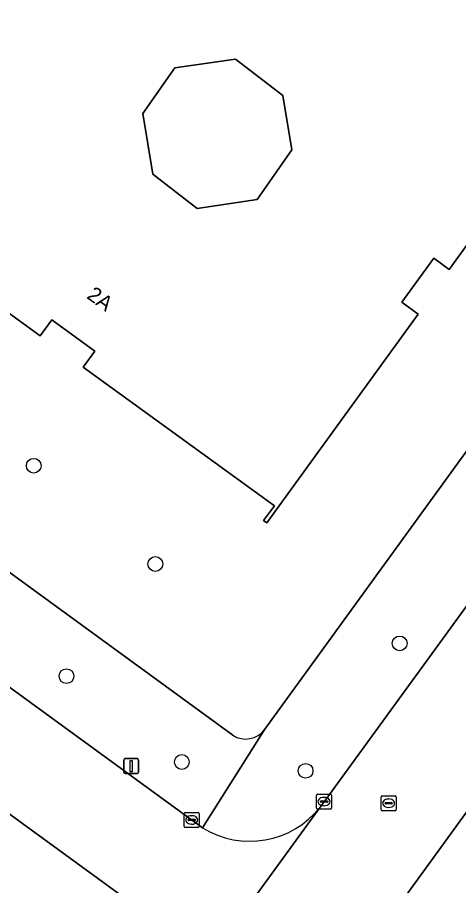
# Model space of a CAD drawing. Extents: x 159674 to 160531, y 382172 to 382904.
# Drawn here: x 160111.2 to 160140.5, y 382380.6 to 382438.2 of the extents above; entities that cross this region are included whole.
import ezdxf

# ---------------------------------------------------------------- set-up
doc = ezdxf.new("R2010")
doc.units = 0
for name, color, linetype in [('IMGEO_Boom', 7, 'Continuous'), ('IMGEO_Erf', 7, 'Continuous'), ('IMGEO_Kolk', 7, 'Continuous'), ('IMGEO_Lichtmast', 7, 'Continuous'), ('IMGEO_Pand', 7, 'Continuous'), ('IMGEO_Pand_nummerreeks', 7, 'Continuous'), ('IMGEO_Rijbaan_lokaal_gesloten', 7, 'Continuous'), ('IMGEO_Rijbaan_lokaal_open', 7, 'Continuous'), ('IMGEO_Rioolput', 7, 'Continuous'), ('IMGEO_Voetpad_open', 7, 'Continuous')]:
    doc.layers.add(name, color=color, linetype=linetype)

msp = doc.modelspace()

# ---------------------------------------------------------------- linework, layer by layer
at = {"layer": 'IMGEO_Boom'}
for centre in [(160112.252, 382408.448), (160120.326, 382401.93), (160136.553, 382396.66), (160114.425, 382394.485), (160122.087, 382388.792), (160130.305, 382388.206)]:
    msp.add_circle(centre, 0.489, dxfattribs=at)
at = {"layer": 'IMGEO_Erf'}
for points in [[(160095.853, 382488.776), (160093.109, 382485.042), (160086.78, 382476.254), (160084.42, 382472.917), (160083.291, 382471.347), (160082.163, 382469.777), (160081.035, 382468.207), (160079.906, 382466.638), (160078.778, 382465.068), (160077.649, 382463.498), (160076.521, 382461.928), (160075.392, 382460.359), (160074.264, 382458.789), (160073.136, 382457.219), (160072.007, 382455.649), (160068.6, 382451.01), (160062.271, 382442.237), (160059.604, 382438.555), (160125.462, 382390.566)], [(160127.601, 382390.967), (160163.121, 382439.912), (160095.853, 382488.776)], [(160136.317, 382443.627), (160150.083, 382433.637), (160149.925, 382433.419), (160148.987, 382434.099), (160139.829, 382421.48), (160138.814, 382422.216), (160136.697, 382419.3), (160137.776, 382418.517), (160127.72, 382404.66), (160127.519, 382404.805), (160128.233, 382405.79), (160115.542, 382415), (160116.31, 382416.057), (160113.45, 382418.133), (160112.674, 382417.064), (160100.019, 382426.248), (160099.35, 382425.327), (160099.082, 382425.521), (160110.426, 382441.152)]]:
    msp.add_lwpolyline(points, dxfattribs=at)
msp.add_lwpolyline([(160121.623, 382434.844), (160119.486, 382431.823), (160120.153, 382427.795), (160123.094, 382425.526), (160127.09, 382426.109), (160129.389, 382429.403), (160128.791, 382433.014), (160125.655, 382435.433)], close=True, dxfattribs=at)
msp.add_arc((160126.319, 382391.898), 1.584, 237.23232, 324.00376, dxfattribs=at)
at = {"layer": 'IMGEO_Kolk'}
for p, q in [((160131.028, 382385.738), (160131.028, 382386.59)), ((160131.103, 382386.664), (160131.955, 382386.664)), ((160131.516, 382386.444), (160131.541, 382386.444)), ((160132.029, 382386.59), (160132.029, 382385.738)), ((160131.287, 382386.158), (160131.287, 382386.17)), ((160131.725, 382386.121), (160131.327, 382386.121)), ((160131.33, 382386.207), (160131.728, 382386.207)), ((160131.539, 382385.884), (160131.514, 382385.884)), ((160131.771, 382386.17), (160131.771, 382386.158)), ((160122.242, 382384.521), (160122.242, 382385.373)), ((160122.317, 382385.447), (160123.169, 382385.447)), ((160122.73, 382385.227), (160122.755, 382385.227)), ((160123.243, 382385.373), (160123.243, 382384.521)), ((160131.955, 382385.664), (160131.103, 382385.664)), ((160122.501, 382384.941), (160122.501, 382384.953)), ((160122.939, 382384.904), (160122.541, 382384.904)), ((160122.544, 382384.99), (160122.942, 382384.99)), ((160122.753, 382384.667), (160122.728, 382384.667)), ((160122.985, 382384.953), (160122.985, 382384.941)), ((160123.169, 382384.447), (160122.317, 382384.447))]:
    msp.add_line(p, q, dxfattribs=at)
for points in [[(160131.028, 382385.738), (160131.028, 382386.59)], [(160131.103, 382386.664), (160131.955, 382386.664)], [(160132.029, 382386.59), (160132.029, 382385.738)], [(160122.242, 382384.521), (160122.242, 382385.373)], [(160122.317, 382385.447), (160123.169, 382385.447)], [(160123.243, 382385.373), (160123.243, 382384.521)], [(160131.955, 382385.664), (160131.103, 382385.664)], [(160123.169, 382384.447), (160122.317, 382384.447)]]:
    msp.add_lwpolyline(points, dxfattribs=at)
for centre, radius, start, end in [((160131.105, 382386.588), 0.0765, 91.55205, 178.44795), ((160131.105, 382386.588), 0.0765, 91.55205, 178.44795), ((160131.953, 382386.588), 0.0765, 1.55205, 88.44795), ((160131.953, 382386.588), 0.0765, 1.55205, 88.44795), ((160131.327, 382386.167), 0.0403, 85.87752, 175.75265), ((160131.324, 382386.157), 0.0366, 178.93798, 274.71019), ((160131.728, 382386.164), 0.043, 264.86636, 352.45326), ((160131.732, 382386.169), 0.0386, 1.73085, 96.63898), ((160122.319, 382385.371), 0.0765, 91.55205, 178.44795), ((160122.319, 382385.371), 0.0765, 91.55205, 178.44795), ((160123.167, 382385.371), 0.0765, 1.55205, 88.44795), ((160123.167, 382385.371), 0.0765, 1.55205, 88.44795), ((160131.105, 382385.74), 0.0765, 181.55205, 268.44795), ((160131.105, 382385.74), 0.0765, 181.55205, 268.44795), ((160131.953, 382385.74), 0.0765, 271.55205, 358.44795), ((160131.953, 382385.74), 0.0765, 271.55205, 358.44795), ((160122.541, 382384.95), 0.0403, 85.87752, 175.75265), ((160122.538, 382384.94), 0.0366, 178.93798, 274.71019), ((160122.942, 382384.947), 0.043, 264.86636, 352.45326), ((160122.946, 382384.952), 0.0386, 1.73085, 96.63898), ((160122.319, 382384.523), 0.0765, 181.55205, 268.44795), ((160122.319, 382384.523), 0.0765, 181.55205, 268.44795), ((160123.167, 382384.523), 0.0765, 271.55205, 358.44795), ((160123.167, 382384.523), 0.0765, 271.55205, 358.44795)]:
    msp.add_arc(centre, radius, start, end, dxfattribs=at)
for centre, major_axis, ratio, start_param, end_param in [((160131.515, 382386.164), (-0.387, 0.002), 0.722429, 4.712389, 7.853982), ((160131.54, 382386.164), (-0.39, 0.002), 0.717154, 1.570796, 4.712389), ((160122.729, 382384.947), (-0.387, 0.002), 0.722429, 4.712389, 7.853982), ((160122.754, 382384.947), (-0.39, 0.002), 0.717154, 1.570796, 4.712389)]:
    msp.add_ellipse(centre, major_axis=major_axis, ratio=ratio, start_param=start_param, end_param=end_param, dxfattribs=at)
at = {"layer": 'IMGEO_Lichtmast'}
for p, q in [((160118.226, 382388.118), (160118.226, 382388.918)), ((160118.226, 382388.918), (160118.226, 382388.118)), ((160118.326, 382389.018), (160119.116, 382389.018)), ((160119.116, 382389.018), (160118.326, 382389.018)), ((160119.216, 382388.918), (160119.216, 382388.118)), ((160119.216, 382388.118), (160119.216, 382388.918)), ((160119.116, 382388.018), (160118.326, 382388.018)), ((160118.326, 382388.018), (160119.116, 382388.018))]:
    msp.add_line(p, q, dxfattribs=at)
msp.add_lwpolyline([(160118.646, 382388.893), (160118.796, 382388.893), (160118.796, 382388.143), (160118.646, 382388.143), (160118.646, 382388.893)], dxfattribs=at)
for centre, start, end in [((160118.326, 382388.918), 90, 180), ((160118.326, 382388.918), 90, 180), ((160119.116, 382388.918), 0, 90), ((160119.116, 382388.918), 360, 90), ((160118.326, 382388.118), 180, 270), ((160118.326, 382388.118), 180, 270), ((160119.116, 382388.118), 270, 0), ((160119.116, 382388.118), 270, 0)]:
    msp.add_arc(centre, 0.1, start, end, dxfattribs=at)
at = {"layer": 'IMGEO_Pand'}
msp.add_lwpolyline([(160110.426, 382441.152), (160099.082, 382425.521), (160099.35, 382425.327), (160100.019, 382426.248), (160112.674, 382417.064), (160113.45, 382418.133), (160116.31, 382416.057), (160115.542, 382415), (160128.233, 382405.79), (160127.519, 382404.805), (160127.72, 382404.66), (160137.776, 382418.517), (160136.697, 382419.3), (160138.814, 382422.216), (160139.829, 382421.48), (160148.987, 382434.099), (160149.925, 382433.419), (160150.083, 382433.637), (160136.317, 382443.627)], dxfattribs=at)
msp.add_lwpolyline([(160121.623, 382434.844), (160125.655, 382435.433), (160128.791, 382433.014), (160129.389, 382429.403), (160127.09, 382426.109), (160123.094, 382425.526), (160120.153, 382427.795), (160119.486, 382431.823)], close=True, dxfattribs=at)
at = {"layer": 'IMGEO_Rijbaan_lokaal_gesloten'}
msp.add_lwpolyline([(160179.328, 382451.773), (160168.227, 382436.541), (160167.872, 382436.054), (160131.527, 382386.158), (160131.264, 382385.796), (160120.578, 382371.104), (160120.218, 382370.61), (160117.262, 382366.539), (160095.963, 382337.199), (160095.222, 382336.136), (160101.268, 382330.867), (160134.37, 382376.353), (160143.85, 382389.399), (160143.915, 382389.491), (160166.91, 382421.18), (160176.58, 382434.549), (160182.656, 382442.82)], dxfattribs=at)
at = {"layer": 'IMGEO_Rijbaan_lokaal_open'}
for points in [[(160123.455, 382384.426), (160018.366, 382460.946)], [(160014.616, 382455.167), (160030.935, 382443.3), (160034.415, 382440.769), (160099.29, 382393.592), (160102.339, 382391.375), (160119.102, 382379.184)], [(160143.85, 382389.399), (160134.37, 382376.353)], [(160120.578, 382371.104), (160131.264, 382385.796)]]:
    msp.add_lwpolyline(points, dxfattribs=at)
msp.add_arc((160126.595, 382389.47), 5.942, 238.10086, 321.80039, dxfattribs=at)
at = {"layer": 'IMGEO_Rioolput'}
for p, q in [((160135.317, 382385.63), (160135.317, 382386.482)), ((160135.392, 382386.556), (160136.244, 382386.556)), ((160136.318, 382386.482), (160136.318, 382385.63)), ((160135.576, 382386.05), (160135.576, 382386.062)), ((160136.014, 382386.013), (160135.616, 382386.013)), ((160135.619, 382386.099), (160136.017, 382386.099)), ((160135.828, 382385.776), (160135.803, 382385.776)), ((160135.805, 382386.336), (160135.83, 382386.336)), ((160136.06, 382386.062), (160136.06, 382386.05)), ((160136.244, 382385.556), (160135.392, 382385.556))]:
    msp.add_line(p, q, dxfattribs=at)
for points in [[(160135.317, 382385.63), (160135.317, 382386.482)], [(160135.392, 382386.556), (160136.244, 382386.556)], [(160136.318, 382386.482), (160136.318, 382385.63)], [(160136.244, 382385.556), (160135.392, 382385.556)]]:
    msp.add_lwpolyline(points, dxfattribs=at)
for centre, radius, start, end in [((160135.394, 382386.48), 0.0765, 91.55205, 178.44795), ((160135.394, 382386.48), 0.0765, 91.55205, 178.44795), ((160136.242, 382386.48), 0.0765, 1.55205, 88.44795), ((160136.242, 382386.48), 0.0765, 1.55205, 88.44795), ((160135.616, 382386.059), 0.0403, 85.87752, 175.75265), ((160135.613, 382386.049), 0.0366, 178.93798, 274.71019), ((160136.017, 382386.056), 0.043, 264.86636, 352.45326), ((160136.021, 382386.061), 0.0386, 1.73085, 96.63898), ((160135.394, 382385.632), 0.0765, 181.55205, 268.44795), ((160135.394, 382385.632), 0.0765, 181.55205, 268.44795), ((160136.242, 382385.632), 0.0765, 271.55205, 358.44795), ((160136.242, 382385.632), 0.0765, 271.55205, 358.44795)]:
    msp.add_arc(centre, radius, start, end, dxfattribs=at)
for centre, major_axis, ratio, start_param, end_param in [((160135.804, 382386.056), (-0.387, 0.002), 0.722429, 4.712389, 7.853982), ((160135.829, 382386.056), (-0.39, 0.002), 0.717154, 1.570796, 4.712389)]:
    msp.add_ellipse(centre, major_axis=major_axis, ratio=ratio, start_param=start_param, end_param=end_param, dxfattribs=at)
at = {"layer": 'IMGEO_Voetpad_open'}
for points in [[(160018.366, 382460.946), (160123.455, 382384.426), (160127.601, 382390.967)], [(160011.345, 382453.23), (160033.01, 382437.511), (160034.251, 382436.61), (160034.768, 382437.312), (160083.531, 382401.81), (160085.455, 382400.41), (160110.564, 382382.129), (160106.732, 382376.818), (160104.611, 382373.905), (160105.953, 382372.892), (160111.288, 382369.019), (160119.102, 382379.184), (160102.339, 382391.375), (160102.045, 382390.971), (160098.996, 382393.188), (160099.29, 382393.592), (160034.415, 382440.769)], [(160168.726, 382443.746), (160163.121, 382439.912), (160127.601, 382390.967), (160123.455, 382384.426)], [(160125.462, 382390.566), (160059.604, 382438.555), (160062.271, 382442.237)], [(160131.264, 382385.796), (160131.527, 382386.158), (160167.872, 382436.054)]]:
    msp.add_lwpolyline(points, dxfattribs=at)
for centre, radius, start, end in [((160126.319, 382391.898), 1.584, 237.23232, 324.00376), ((160126.595, 382389.47), 5.942, 238.10086, 321.80039)]:
    msp.add_arc(centre, radius, start, end, dxfattribs=at)

# ---------------------------------------------------------------- texts
at = {"layer": 'IMGEO_Pand_nummerreeks'}
msp.add_text('2A', height=1, rotation=324.02398, dxfattribs=at).set_placement((160115.71, 382419.607))

doc.saveas('drawing.dxf')
